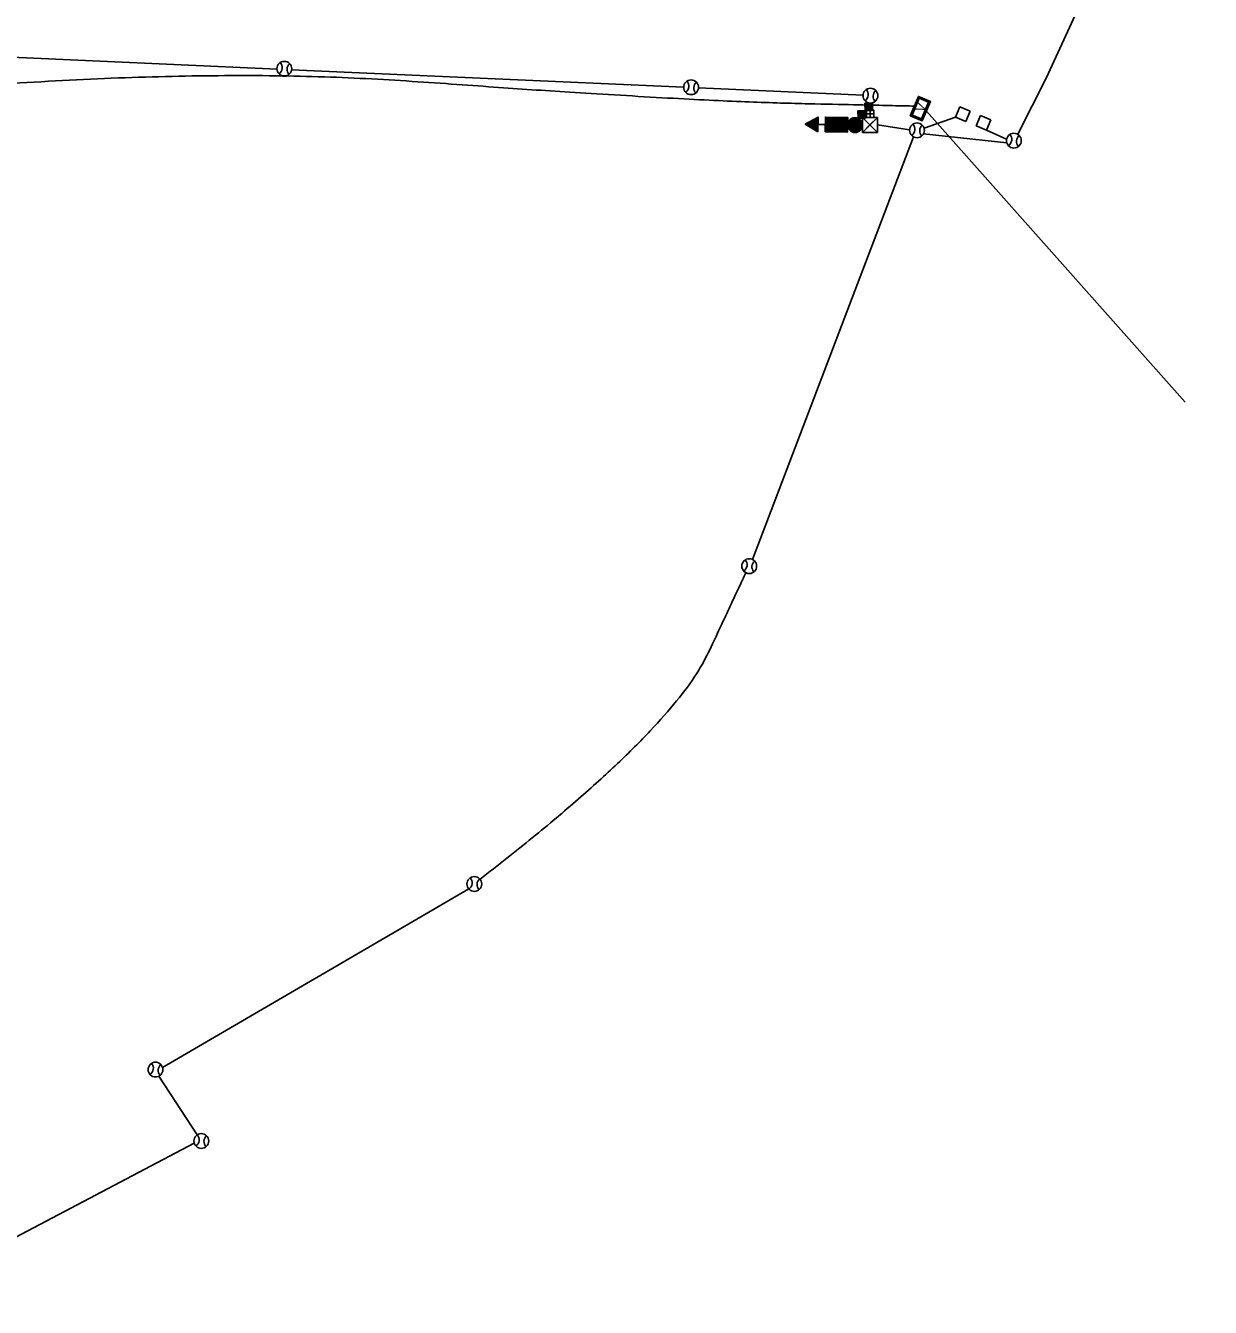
# Model space of a CAD drawing. Extents: x 0 to 2149228, y 0 to 2148913.
# Drawn here: x 596619 to 597259, y 230512 to 231204 of the extents above; entities that cross this region are included whole.
import ezdxf

# ---------------------------------------------------------------- set-up
doc = ezdxf.new("R2010")
doc.units = 0
for name, color, linetype in [('P_FTMS_2013 _CONDUIT', 7, 'Continuous'), ('P_FTMS_2013_NOT_CONDUIT', 7, 'Continuous'), ('P_TC_Drums_100_50', 7, 'Continuous')]:
    doc.layers.add(name, color=color, linetype=linetype)

# ---------------------------------------------------------------- blocks, each defined once
blk = doc.blocks.new('PB24X42')
at = {"layer": 'P_TC_Drums_100_50'}
blk.add_circle((0, 0), 2, dxfattribs=at)
for centre, start, end in [((-2.59, 0.09), 308.3742, 47.6044), ((2.73, 0.07), 134.4184, 228.4474)]:
    blk.add_arc(centre, 2, start, end, dxfattribs=at)

msp = doc.modelspace()

# ---------------------------------------------------------------- linework, layer by layer
at = {"layer": 'P_FTMS_2013 _CONDUIT'}
for p, q in [((596494.61, 231192.26), (596754.65, 231180.73)), ((596762.45, 231180.38), (596974.21, 231170.99)), ((596982.06, 231170.64), (597070.99, 231166.7)), ((597074.63, 231162.37), (597074.79, 231158.61)), ((597105.18, 231158.02), (597244.97, 231000.96)), ((597098.28, 231144.1), (597011.36, 230915.88)), ((597078.74, 231150.55), (597096.14, 231148)), ((597103.68, 231145.81), (597148.59, 231140.86)), ((596858.07, 230738.15), (596692.78, 230641.72)), ((596690.8, 230636.97), (596711.48, 230605.29)), ((596709.88, 230600.75), (596541.35, 230512.12))]:
    msp.add_line(p, q, dxfattribs=at)
msp.add_lwpolyline([(597154.48, 231145.56), (597169.99, 231176.22), (597185.43, 231209.9), (597207.92, 231241.83), (597258.51, 231309.46)], dxfattribs=at)
for points in [[(596475.41, 231160.46), (596683.57, 231184.54), (596974.51, 231163.47), (597098.68, 231160.74), (597098.68, 231160.74), (597098.68, 231160.74)], [(596864.19, 230743.3), (596967.6, 230823.08), (597007.68, 230908.78), (597007.68, 230908.78)]]:
    msp.add_open_spline(points, degree=2, dxfattribs=at)
at = {"layer": 'P_FTMS_2013_NOT_CONDUIT'}
for p, q in [((597072.28, 231154.27), (597068.15, 231158.14)), ((597068.34, 231158.14), (597068.16, 231157.94)), ((597071.94, 231154.26), (597068.16, 231157.8)), ((597068.68, 231158.15), (597068.17, 231157.6)), ((597069.02, 231158.17), (597068.18, 231157.27)), ((597069.36, 231158.18), (597068.19, 231156.93)), ((597069.7, 231158.19), (597068.2, 231156.59)), ((597070.04, 231158.2), (597068.21, 231156.25)), ((597070.38, 231158.21), (597068.22, 231155.91)), ((597070.72, 231158.22), (597068.23, 231155.57)), ((597071.06, 231158.23), (597068.24, 231155.23)), ((597071.4, 231158.24), (597068.25, 231154.89)), ((597071.73, 231158.25), (597068.27, 231154.55)), ((597072.07, 231158.26), (597068.28, 231154.21)), ((597072.27, 231154.61), (597068.49, 231158.15)), ((597072.16, 231158), (597068.55, 231154.15)), ((597072.25, 231154.95), (597068.83, 231158.16)), ((597072.17, 231157.66), (597068.88, 231154.16)), ((597072.24, 231155.29), (597069.17, 231158.17)), ((597072.23, 231155.63), (597069.51, 231158.18)), ((597072.22, 231155.97), (597069.85, 231158.19)), ((597072.21, 231156.3), (597070.18, 231158.2)), ((597072.2, 231156.64), (597070.52, 231158.21)), ((597072.19, 231156.98), (597070.86, 231158.23)), ((597072.18, 231157.32), (597071.2, 231158.24)), ((597072.17, 231157.66), (597071.54, 231158.25)), ((597072.16, 231158), (597071.88, 231158.26)), ((597076.15, 231158.4), (597072.02, 231162.27)), ((597072.21, 231162.27), (597072.02, 231162.07)), ((597072.55, 231162.28), (597072.03, 231161.73)), ((597075.81, 231158.39), (597072.03, 231161.93)), ((597075.47, 231158.38), (597072.04, 231161.59)), ((597072.89, 231162.29), (597072.05, 231161.39)), ((597075.13, 231158.36), (597072.05, 231161.25)), ((597073.23, 231162.3), (597072.06, 231161.05)), ((597074.79, 231158.35), (597072.06, 231160.91)), ((597073.57, 231162.32), (597072.07, 231160.72)), ((597074.45, 231158.34), (597072.07, 231160.57)), ((597073.91, 231162.33), (597072.08, 231160.38)), ((597074.11, 231158.33), (597072.08, 231160.23)), ((597074.25, 231162.34), (597072.09, 231160.04)), ((597073.77, 231158.32), (597072.09, 231159.89)), ((597074.59, 231162.35), (597072.1, 231159.7)), ((597074.93, 231162.36), (597072.11, 231159.36)), ((597073.43, 231158.31), (597072.11, 231159.55)), ((597075.26, 231162.37), (597072.12, 231159.02)), ((597073.09, 231158.3), (597072.12, 231159.21)), ((597075.6, 231162.38), (597072.13, 231158.68)), ((597072.75, 231158.29), (597072.13, 231158.87)), ((597075.94, 231162.39), (597072.14, 231158.34)), ((597072.41, 231158.28), (597072.14, 231158.53)), ((597076.13, 231158.74), (597072.36, 231162.28)), ((597076.02, 231162.13), (597072.41, 231158.28)), ((597076.12, 231159.08), (597072.7, 231162.29)), ((597076.04, 231161.79), (597072.75, 231158.29)), ((597076.11, 231159.41), (597073.04, 231162.3)), ((597076.05, 231161.45), (597073.09, 231158.3)), ((597076.1, 231159.75), (597073.37, 231162.31)), ((597076.06, 231161.11), (597073.43, 231158.31)), ((597076.09, 231160.09), (597073.71, 231162.32)), ((597076.07, 231160.77), (597073.77, 231158.32)), ((597076.08, 231160.43), (597074.05, 231162.33)), ((597076.08, 231160.43), (597074.11, 231158.33)), ((597076.07, 231160.77), (597074.39, 231162.34)), ((597076.09, 231160.09), (597074.45, 231158.34)), ((597076.06, 231161.11), (597074.73, 231162.35)), ((597076.1, 231159.75), (597074.79, 231158.35)), ((597074.79, 231158.61), (597074.81, 231154.61)), ((597076.05, 231161.45), (597075.07, 231162.36)), ((597076.11, 231159.41), (597075.13, 231158.36)), ((597076.04, 231161.79), (597075.41, 231162.38)), ((597076.12, 231159.08), (597075.47, 231158.38)), ((597076.02, 231162.13), (597075.75, 231162.39)), ((597076.13, 231158.74), (597075.81, 231158.39)), ((597123.32, 231160.34), (597120.98, 231154.81)), ((597128.84, 231158.01), (597123.32, 231160.34)), ((597126.51, 231152.48), (597128.84, 231158.01)), ((597039.75, 231150.91), (597039.75, 231150.91)), ((597039.94, 231150.81), (597040.55, 231151.35)), ((597040.54, 231150.45), (597039.95, 231151.01)), ((597040.19, 231150.66), (597041.36, 231151.84)), ((597041.33, 231149.94), (597040.2, 231151.16)), ((597040.39, 231150.56), (597042.16, 231152.28)), ((597042.13, 231149.48), (597040.4, 231151.25)), ((597040.59, 231150.4), (597042.97, 231152.72)), ((597042.92, 231149.02), (597040.6, 231151.4)), ((597040.84, 231150.3), (597043.78, 231153.16)), ((597043.72, 231148.56), (597040.85, 231151.5)), ((597041.04, 231150.15), (597044.58, 231153.65)), ((597044.51, 231148.05), (597041.06, 231151.65)), ((597041.23, 231150.04), (597045.39, 231154.09)), ((597045.35, 231147.59), (597041.26, 231151.74)), ((597041.43, 231149.89), (597046.24, 231154.53)), ((597046.15, 231147.13), (597041.46, 231151.89)), ((597041.68, 231149.79), (597046.7, 231154.67)), ((597046.6, 231146.97), (597041.71, 231151.99)), ((597041.88, 231149.64), (597046.69, 231154.32)), ((597046.6, 231147.32), (597041.91, 231152.14)), ((597042.08, 231149.53), (597046.69, 231153.97)), ((597046.6, 231147.67), (597042.11, 231152.23)), ((597042.33, 231149.38), (597046.68, 231153.62)), ((597046.61, 231148.02), (597042.37, 231152.38)), ((597042.52, 231149.28), (597046.68, 231153.32)), ((597046.61, 231148.32), (597042.57, 231152.48)), ((597042.72, 231149.12), (597046.67, 231152.97)), ((597046.62, 231148.67), (597042.77, 231152.62)), ((597042.97, 231149.02), (597046.67, 231152.62)), ((597046.62, 231149.02), (597043.02, 231152.72)), ((597043.17, 231148.87), (597046.66, 231152.27)), ((597046.63, 231149.37), (597043.22, 231152.87)), ((597043.37, 231148.77), (597046.66, 231151.92)), ((597046.63, 231149.72), (597043.42, 231152.97)), ((597043.57, 231148.61), (597046.66, 231151.62)), ((597046.63, 231150.02), (597043.62, 231153.11)), ((597043.82, 231148.51), (597046.65, 231151.27)), ((597046.64, 231150.37), (597043.88, 231153.21)), ((597044.01, 231148.36), (597046.65, 231150.92)), ((597046.64, 231150.72), (597044.08, 231153.36)), ((597046.65, 231151.07), (597044.28, 231153.45)), ((597046.65, 231151.37), (597044.53, 231153.6)), ((597046.66, 231151.72), (597044.73, 231153.7)), ((597046.66, 231152.07), (597044.93, 231153.85)), ((597046.67, 231152.42), (597045.19, 231153.94)), ((597046.67, 231152.77), (597045.39, 231154.09)), ((597046.67, 231153.07), (597045.59, 231154.19)), ((597046.68, 231153.42), (597045.79, 231154.34)), ((597046.68, 231153.77), (597046.04, 231154.43)), ((597046.69, 231154.12), (597046.24, 231154.58)), ((597046.69, 231154.47), (597046.45, 231154.68)), ((597050.65, 231150.77), (597046.65, 231150.82)), ((597046.7, 231154.77), (597046.7, 231154.82)), ((597050.59, 231146.77), (597058.7, 231154.67)), ((597050.6, 231147.47), (597058, 231154.68)), ((597050.6, 231147.12), (597058.35, 231154.67)), ((597050.61, 231148.17), (597057.35, 231154.69)), ((597050.61, 231147.82), (597057.65, 231154.68)), ((597050.62, 231149.17), (597056.3, 231154.7)), ((597050.62, 231148.47), (597057, 231154.69)), ((597050.62, 231148.82), (597056.65, 231154.69)), ((597050.63, 231149.82), (597055.65, 231154.71)), ((597050.63, 231149.52), (597056, 231154.7)), ((597050.64, 231150.52), (597054.95, 231154.72)), ((597050.64, 231150.17), (597055.3, 231154.71)), ((597050.65, 231151.22), (597054.3, 231154.73)), ((597050.65, 231151.52), (597053.95, 231154.73)), ((597050.65, 231150.87), (597054.6, 231154.72)), ((597055.34, 231146.71), (597050.65, 231151.52)), ((597054.99, 231146.72), (597050.65, 231151.22)), ((597054.64, 231146.72), (597050.65, 231150.87)), ((597050.66, 231152.22), (597053.25, 231154.74)), ((597050.66, 231151.87), (597053.6, 231154.73)), ((597055.99, 231146.7), (597050.66, 231152.22)), ((597055.69, 231146.71), (597050.66, 231151.87)), ((597050.67, 231152.92), (597052.6, 231154.75)), ((597050.67, 231152.57), (597052.9, 231154.74)), ((597056.69, 231146.69), (597050.67, 231152.92)), ((597056.34, 231146.7), (597050.67, 231152.57)), ((597050.68, 231153.57), (597051.9, 231154.76)), ((597050.68, 231153.22), (597052.25, 231154.75)), ((597057.39, 231146.68), (597050.68, 231153.57)), ((597057.04, 231146.69), (597050.68, 231153.22)), ((597050.69, 231154.57), (597050.9, 231154.77)), ((597050.69, 231153.92), (597051.55, 231154.76)), ((597050.69, 231154.27), (597051.25, 231154.76)), ((597058.39, 231146.67), (597050.69, 231154.57)), ((597058.04, 231146.68), (597050.69, 231154.27)), ((597057.69, 231146.68), (597050.69, 231153.92)), ((597058.74, 231146.67), (597050.85, 231154.77)), ((597050.94, 231146.77), (597059.05, 231154.66)), ((597059.09, 231146.66), (597051.2, 231154.77)), ((597051.24, 231146.76), (597059.35, 231154.66)), ((597059.39, 231146.66), (597051.5, 231154.76)), ((597051.59, 231146.76), (597059.7, 231154.66)), ((597059.74, 231146.65), (597051.85, 231154.76)), ((597051.94, 231146.76), (597060.05, 231154.65)), ((597060.09, 231146.65), (597052.2, 231154.75)), ((597052.29, 231146.75), (597060.4, 231154.65)), ((597060.44, 231146.65), (597052.55, 231154.75)), ((597052.64, 231146.75), (597060.75, 231154.64)), ((597060.74, 231146.64), (597052.85, 231154.74)), ((597052.94, 231146.74), (597061.05, 231154.64)), ((597061.09, 231146.64), (597053.2, 231154.74)), ((597053.29, 231146.74), (597061.4, 231154.63)), ((597061.44, 231146.63), (597053.55, 231154.74)), ((597053.64, 231146.73), (597061.75, 231154.63)), ((597061.79, 231146.63), (597053.9, 231154.73)), ((597053.99, 231146.73), (597062.1, 231154.62)), ((597062.14, 231146.62), (597054.25, 231154.73)), ((597054.34, 231146.72), (597062.45, 231154.62)), ((597062.44, 231146.62), (597054.55, 231154.72)), ((597054.64, 231146.72), (597062.7, 231154.57)), ((597062.6, 231146.87), (597054.9, 231154.72)), ((597054.99, 231146.72), (597062.69, 231154.22)), ((597062.6, 231147.22), (597055.25, 231154.71)), ((597055.34, 231146.71), (597062.69, 231153.87)), ((597062.6, 231147.52), (597055.6, 231154.71)), ((597055.69, 231146.71), (597062.68, 231153.57)), ((597062.61, 231147.87), (597055.95, 231154.7)), ((597055.99, 231146.7), (597062.68, 231153.22)), ((597062.61, 231148.22), (597056.25, 231154.7)), ((597056.34, 231146.7), (597062.67, 231152.87)), ((597062.62, 231148.57), (597056.6, 231154.7)), ((597056.69, 231146.69), (597062.67, 231152.52)), ((597062.62, 231148.87), (597056.95, 231154.69)), ((597057.04, 231146.69), (597062.66, 231152.17)), ((597062.63, 231149.22), (597057.3, 231154.69)), ((597057.39, 231146.68), (597062.66, 231151.87)), ((597062.63, 231149.57), (597057.65, 231154.68)), ((597057.69, 231146.68), (597062.66, 231151.52)), ((597062.63, 231149.92), (597057.95, 231154.68)), ((597058.04, 231146.68), (597062.65, 231151.17)), ((597062.64, 231150.27), (597058.3, 231154.67)), ((597058.39, 231146.67), (597062.65, 231150.82)), ((597062.64, 231150.57), (597058.65, 231154.67)), ((597062.65, 231150.92), (597059, 231154.66)), ((597062.65, 231151.27), (597059.3, 231154.66)), ((597062.66, 231151.62), (597059.65, 231154.66)), ((597062.66, 231151.97), (597060, 231154.65)), ((597062.67, 231152.27), (597060.35, 231154.65)), ((597062.67, 231152.62), (597060.7, 231154.64)), ((597062.67, 231152.97), (597061, 231154.64)), ((597062.68, 231153.32), (597061.35, 231154.63)), ((597062.68, 231153.62), (597061.7, 231154.63)), ((597062.69, 231153.97), (597062.05, 231154.62)), ((597062.69, 231154.32), (597062.4, 231154.62)), ((597062.62, 231150.29), (597066.68, 231154.24)), ((597062.63, 231150.64), (597066.58, 231154.49)), ((597066.58, 231146.74), (597062.63, 231150.79)), ((597062.67, 231149.99), (597066.67, 231153.89)), ((597062.68, 231150.99), (597066.23, 231154.44)), ((597066.58, 231147.09), (597062.69, 231151.09)), ((597062.72, 231149.69), (597066.67, 231153.54)), ((597062.74, 231151.39), (597065.83, 231154.4)), ((597066.59, 231147.44), (597062.74, 231151.39)), ((597062.76, 231149.44), (597066.66, 231153.19)), ((597066.59, 231147.79), (597062.79, 231151.64)), ((597062.86, 231149.18), (597066.66, 231152.89)), ((597062.9, 231151.88), (597065.33, 231154.25)), ((597066.6, 231148.09), (597062.9, 231151.88)), ((597062.96, 231148.93), (597066.65, 231152.54)), ((597066.6, 231148.44), (597063, 231152.13)), ((597063.05, 231148.68), (597066.65, 231152.19)), ((597066.61, 231148.79), (597063.1, 231152.38)), ((597063.15, 231152.48), (597064.72, 231153.96)), ((597063.2, 231148.48), (597066.65, 231151.84)), ((597066.61, 231149.14), (597063.25, 231152.58)), ((597063.3, 231148.28), (597066.64, 231151.49)), ((597066.61, 231149.49), (597063.36, 231152.78)), ((597063.45, 231148.08), (597066.64, 231151.19)), ((597066.62, 231149.79), (597063.51, 231152.98)), ((597063.59, 231147.88), (597066.63, 231150.84)), ((597066.62, 231150.14), (597063.66, 231153.17)), ((597066.63, 231150.49), (597063.86, 231153.32)), ((597066.63, 231150.84), (597064.02, 231153.52)), ((597066.64, 231151.19), (597064.22, 231153.67)), ((597066.64, 231151.49), (597064.42, 231153.82)), ((597066.65, 231151.84), (597064.62, 231153.91)), ((597066.65, 231152.19), (597064.82, 231154.06)), ((597066.65, 231152.54), (597065.08, 231154.16)), ((597066.66, 231152.89), (597065.33, 231154.25)), ((597066.66, 231153.19), (597065.58, 231154.35)), ((597066.67, 231153.54), (597065.83, 231154.4)), ((597066.67, 231153.89), (597066.13, 231154.44)), ((597066.68, 231154.24), (597066.43, 231154.49)), ((597066.58, 231147.09), (597070.58, 231150.99)), ((597066.58, 231146.74), (597070.63, 231150.68)), ((597066.59, 231147.79), (597070.49, 231151.54)), ((597066.59, 231147.44), (597070.54, 231151.29)), ((597066.6, 231148.44), (597070.3, 231152.04)), ((597066.6, 231148.09), (597070.39, 231151.79)), ((597066.61, 231149.49), (597069.96, 231152.69)), ((597066.61, 231149.14), (597070.05, 231152.49)), ((597066.61, 231148.79), (597070.2, 231152.29)), ((597066.62, 231150.14), (597069.66, 231153.1)), ((597066.62, 231149.79), (597069.81, 231152.9)), ((597066.63, 231150.84), (597069.32, 231153.45)), ((597066.63, 231150.49), (597069.46, 231153.25)), ((597069.59, 231147.8), (597066.63, 231150.84)), ((597066.64, 231151.49), (597068.92, 231153.76)), ((597066.64, 231151.19), (597069.12, 231153.6)), ((597069.9, 231148.19), (597066.64, 231151.49)), ((597069.75, 231148), (597066.64, 231151.19)), ((597066.65, 231152.54), (597068.27, 231154.12)), ((597066.65, 231152.19), (597068.52, 231154.01)), ((597066.65, 231151.84), (597068.72, 231153.86)), ((597070.26, 231148.84), (597066.65, 231152.54)), ((597070.15, 231148.59), (597066.65, 231152.19)), ((597070, 231148.39), (597066.65, 231151.84)), ((597066.66, 231153.19), (597067.78, 231154.32)), ((597066.66, 231152.89), (597068.03, 231154.22)), ((597070.46, 231149.34), (597066.66, 231153.19)), ((597070.36, 231149.09), (597066.66, 231152.89)), ((597066.67, 231153.89), (597067.23, 231154.43)), ((597066.67, 231153.54), (597067.53, 231154.37)), ((597070.57, 231149.89), (597066.67, 231153.89)), ((597070.52, 231149.59), (597066.67, 231153.54)), ((597066.68, 231154.49), (597066.68, 231154.49)), ((597066.68, 231154.49), (597066.68, 231154.49)), ((597066.68, 231154.49), (597066.68, 231154.49)), ((597066.68, 231154.49), (597066.68, 231154.49)), ((597066.68, 231154.24), (597066.93, 231154.48)), ((597070.62, 231150.18), (597066.68, 231154.24)), ((597070.63, 231150.53), (597066.78, 231154.48)), ((597070.58, 231150.89), (597067.13, 231154.43)), ((597070.54, 231151.29), (597067.53, 231154.37)), ((597070.39, 231151.79), (597068.03, 231154.22)), ((597071.6, 231154.25), (597068.17, 231157.46)), ((597071.26, 231154.24), (597068.18, 231157.12)), ((597070.92, 231154.23), (597068.19, 231156.78)), ((597070.58, 231154.21), (597068.2, 231156.44)), ((597070.24, 231154.2), (597068.22, 231156.1)), ((597069.9, 231154.19), (597068.23, 231155.76)), ((597069.56, 231154.18), (597068.24, 231155.42)), ((597069.22, 231154.17), (597068.25, 231155.08)), ((597068.88, 231154.16), (597068.26, 231154.75)), ((597068.55, 231154.15), (597068.27, 231154.41)), ((597070.15, 231152.39), (597068.62, 231153.91)), ((597072.18, 231157.32), (597069.22, 231154.17)), ((597072.19, 231156.98), (597069.56, 231154.18)), ((597072.2, 231156.64), (597069.9, 231154.19)), ((597072.21, 231156.3), (597070.24, 231154.2)), ((597072.22, 231155.97), (597070.58, 231154.21)), ((597078.75, 231146.55), (597070.74, 231154.54)), ((597078.74, 231154.55), (597070.75, 231146.54)), ((597072.23, 231155.63), (597070.92, 231154.23)), ((597072.24, 231155.29), (597071.26, 231154.24)), ((597072.25, 231154.95), (597071.6, 231154.25)), ((597072.27, 231154.61), (597071.94, 231154.26)), ((597072.8, 231156.6), (597076.8, 231156.62)), ((597103.94, 231148.86), (597120.98, 231154.81)), ((597126.51, 231152.48), (597120.98, 231154.81)), ((597134.37, 231155.67), (597132.04, 231150.14)), ((597139.9, 231153.34), (597134.37, 231155.67)), ((597137.57, 231147.81), (597139.9, 231153.34)), ((597044.21, 231148.26), (597046.64, 231150.57)), ((597044.46, 231148.1), (597046.64, 231150.27)), ((597044.66, 231148), (597046.63, 231149.92)), ((597044.86, 231147.85), (597046.63, 231149.57)), ((597045.11, 231147.74), (597046.62, 231149.22)), ((597045.3, 231147.59), (597046.62, 231148.87)), ((597045.5, 231147.49), (597046.62, 231148.57)), ((597045.7, 231147.34), (597046.61, 231148.22)), ((597045.95, 231147.23), (597046.61, 231147.87)), ((597046.15, 231147.08), (597046.6, 231147.52)), ((597046.35, 231146.98), (597046.6, 231147.17)), ((597046.59, 231146.82), (597046.59, 231146.87)), ((597051.24, 231146.76), (597050.6, 231147.47)), ((597050.94, 231146.77), (597050.6, 231147.12)), ((597051.94, 231146.76), (597050.61, 231148.17)), ((597051.59, 231146.76), (597050.61, 231147.82)), ((597052.94, 231146.74), (597050.62, 231149.17)), ((597052.64, 231146.75), (597050.62, 231148.82)), ((597052.29, 231146.75), (597050.62, 231148.47)), ((597053.64, 231146.73), (597050.63, 231149.82)), ((597053.29, 231146.74), (597050.63, 231149.52)), ((597054.34, 231146.72), (597050.64, 231150.52)), ((597053.99, 231146.73), (597050.64, 231150.17)), ((597058.74, 231146.67), (597062.64, 231150.47)), ((597059.09, 231146.66), (597062.64, 231150.17)), ((597059.39, 231146.66), (597062.63, 231149.82)), ((597059.74, 231146.65), (597062.63, 231149.47)), ((597060.09, 231146.65), (597062.62, 231149.12)), ((597060.44, 231146.65), (597062.62, 231148.82)), ((597060.74, 231146.64), (597062.62, 231148.47)), ((597061.09, 231146.64), (597062.61, 231148.12)), ((597061.44, 231146.63), (597062.61, 231147.77)), ((597061.79, 231146.63), (597062.6, 231147.42)), ((597062.14, 231146.62), (597062.6, 231147.12)), ((597062.44, 231146.62), (597062.59, 231146.77)), ((597066.48, 231146.49), (597062.63, 231150.44)), ((597066.13, 231146.54), (597062.67, 231150.09)), ((597065.73, 231146.6), (597062.72, 231149.69)), ((597065.28, 231146.7), (597062.86, 231149.18)), ((597064.63, 231147.01), (597063.1, 231148.58)), ((597063.79, 231147.72), (597066.63, 231150.49)), ((597063.94, 231147.52), (597066.62, 231150.14)), ((597064.14, 231147.37), (597066.62, 231149.79)), ((597064.34, 231147.22), (597066.61, 231149.49)), ((597064.53, 231147.11), (597066.61, 231149.14)), ((597064.73, 231146.96), (597066.61, 231148.79)), ((597064.98, 231146.86), (597066.6, 231148.44)), ((597065.18, 231146.75), (597066.6, 231148.09)), ((597065.48, 231146.65), (597066.59, 231147.79)), ((597065.73, 231146.6), (597066.59, 231147.44)), ((597066.03, 231146.54), (597066.58, 231147.09)), ((597066.33, 231146.49), (597066.58, 231146.74)), ((597066.53, 231146.49), (597066.58, 231146.54)), ((597067.13, 231146.53), (597066.58, 231147.09)), ((597066.83, 231146.48), (597066.58, 231146.74)), ((597066.63, 231146.49), (597066.58, 231146.54)), ((597067.68, 231146.62), (597066.59, 231147.79)), ((597067.43, 231146.58), (597066.59, 231147.44)), ((597068.18, 231146.82), (597066.6, 231148.44)), ((597067.98, 231146.72), (597066.6, 231148.09)), ((597068.83, 231147.16), (597066.61, 231149.49)), ((597068.63, 231147.06), (597066.61, 231149.14)), ((597068.43, 231146.91), (597066.61, 231148.79)), ((597069.24, 231147.45), (597066.62, 231150.14)), ((597069.04, 231147.3), (597066.62, 231149.79)), ((597069.39, 231147.65), (597066.63, 231150.49)), ((597066.68, 231146.49), (597070.63, 231150.33)), ((597067.03, 231146.53), (597070.57, 231149.99)), ((597067.43, 231146.58), (597070.52, 231149.59)), ((597067.88, 231146.67), (597070.36, 231149.09)), ((597068.53, 231146.96), (597070.1, 231148.49)), ((597137.57, 231147.81), (597132.04, 231150.14)), ((597137.57, 231147.81), (597148.5, 231142.9))]:
    msp.add_line(p, q, dxfattribs=at)
for points in [[(597096.49, 231155.53), (597100.86, 231165.95), (597107.36, 231163.23), (597102.99, 231152.81)], [(597096.82, 231155.66), (597101, 231165.63), (597107.03, 231163.1), (597102.86, 231153.13)], [(597097.15, 231155.8), (597101.13, 231165.3), (597106.71, 231162.96), (597102.72, 231153.46)], [(597097.47, 231155.93), (597101.27, 231164.97), (597106.38, 231162.83), (597102.59, 231153.79)], [(597068.28, 231154.14), (597068.15, 231158.14), (597072.15, 231158.27), (597072.28, 231154.27)], [(597072.15, 231158.27), (597072.02, 231162.27), (597076.02, 231162.39), (597076.15, 231158.4)], [(597072.81, 231154.6), (597076.81, 231154.62), (597076.79, 231158.62), (597072.79, 231158.6)], [(597046.59, 231146.82), (597046.7, 231154.82), (597039.75, 231150.91)], [(597062.7, 231154.62), (597050.7, 231154.77), (597050.59, 231146.77), (597062.59, 231146.62)], [(597078.74, 231154.55), (597070.74, 231154.54), (597070.75, 231146.54), (597078.75, 231146.55)], [(597070.74, 231154.54), (597074.74, 231150.54), (597078.74, 231154.55)], [(597070.75, 231146.54), (597074.74, 231150.54), (597078.75, 231146.55)]]:
    msp.add_lwpolyline(points, close=True, dxfattribs=at)
msp.add_circle((597066.63, 231150.49), 4, dxfattribs=at)
for start, end in [(89.25808, 269.25808), (269.25808, 89.25808)]:
    msp.add_arc((597066.63, 231150.49), 4, start, end, dxfattribs=at)

# ---------------------------------------------------------------- block references
at = {"layer": 'P_FTMS_2013_NOT_CONDUIT', "xscale": 2, "yscale": 2.0000000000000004, "rotation": -4.918194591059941}
for p in [(596758.53, 231180.9), (596978.15, 231170.91), (597074.98, 231166.36), (597100.12, 231147.65), (597152.41, 231142.07), (597009.52, 230912.33), (596861.13, 230740.72), (596688.97, 230640.51), (596713.69, 230601.96)]:
    msp.add_blockref('PB24X42', p, dxfattribs=at)

# ---------------------------------------------------------------- texts
at = {"layer": 'P_FTMS_2013_NOT_CONDUIT'}
msp.add_text('V', height=4.96, rotation=67.24707, dxfattribs=at).set_placement((597103.59, 231156.93))

doc.saveas('drawing.dxf')
